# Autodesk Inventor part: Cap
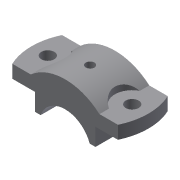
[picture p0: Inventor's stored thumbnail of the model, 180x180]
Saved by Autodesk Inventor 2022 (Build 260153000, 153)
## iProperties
Created: 2009-04
Part Number: Cap
Document SubType Name: Modeling
Designer: Sham
Density: 1 g/cm^3
Material: Generic
Appearance: Default
Author: Sham
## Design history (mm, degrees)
sketch "Sketch1"
  geometry: L1 (-48.857, 23)-(48.857, 23); L2 (48.857, -23)-(-48.857, -23); A1 r 54 centre (0, 0) between (-48.857, 23) and (-48.857, -23); A2 r 54 centre (0, 0) between (48.857, -23) and (48.857, 23); 1 further point
  constraints: 4 end point, 4 point on circle, 2 centre point, 2 coincident, 1 horizontal, 1 parallel, 1 other
  dimensions: "d3" = 54 radius of A1; "d4" = 54 radius of A2; "d5" = 46 distance between parallel lines of L2 L1; "d6" = 23 distance from line of point (0, 0) L1
extrude "Extrusion1" new body sketch "Sketch1" distance "d7" = 12; taper "d8" = 0 deg
sketch "Sketch3"
  geometry: L1 (20.906, 0)-(20.906, -16); L2 (76.906, -0.137)-(76.906, -16.137); L3 (20.906, -16)-(26.23, -16); L4 (71.532, -16.137)-(76.906, -16.137); L5 (76.906, -0.137)-(76.857, 12); L6 (97.714, 0)-(0, 0) reference; L7 (76.857, 12)-(80.606, 12); L8 (17.108, 12)-(20.906, 12); L9 (20.906, 12)-(20.906, 0); L10 (0, 12)-(97.714, 12) reference; A1 r 24 centre (48.857, -24) between (71.532, -16.137) and (26.23, -16); A2 r 48 centre (48.857, -24) between (80.606, 12) and (17.108, 12); 3 further points
  constraints: 16 end point, 4 point on circle, 3 parallel, 3 perpendicular, 2 centre point, 2 coincident, 2 vertical alignment, 1 collinear, 1 midpoint, 1 vertical, 2 other
  dimensions: "d17" = 48 diameter of A1; "d18" = 16 distance of L1.start L1.end; "d19" = 56 distance between parallel lines of L2 L1; "d21" = 8 vertical distance of A1.centre L1.end; "d22" = 48 radius of A2; "d23" = 0 distance from line of L6 L1.start; "d38" = 31.74902 distance of L7.end point (48.857, 12); "d39" = 28 distance from line of point (48.857, 12) L5
extrude "Extrusion2" join sketch "Sketch3" stored distance "d24" = 12; taper "d25" = 0 deg
sketch "Sketch4"
  geometry: 2 further points
  dimensions: "d26" = 78 distance of point (39, 0) point (-39, 0)
hole "Hole1" sketch "Sketch4" at (-39, 0), (39, 0) diameter "d28" = 12; stored, may be unused: countersink angle "d32" = 90 deg, drill point angle "d34" = 118 deg; dims "d29" = 6, "d30" = 4, "d31" = 2, "d33" = 8
sketch "Sketch5"
  geometry: L1 (-31.749, -23)-(-31.749, 23) reference; L2 (-31.749, 14.263)-(-31.749, -14.263); C1 r 6 at (-39, 0) reference; A1 r 16 centre (-39, 0) between (-31.749, -14.263) and (-31.749, 14.263)
  constraints: 2 end point, 2 point on circle, 1 centre point, 1 coincident, 1 collinear, 1 point on line
  dimensions: "d35" = 16 radius of A1
extrude "Extrusion3" cut sketch "Sketch5" distance "d36" = 12; taper "d37" = 0 deg
mirror "Mirror2"
workplane "Work Plane4"
sketch "Sketch6"
  geometry: L1 (-31.749, 0)-(31.749, 0) reference; 1 further point
  dimensions: "d40" = 23 distance from line of L1 point (0, 23)
hole "Hole2" sketch "Sketch6" at (0, 23) diameter "d41" = 6; stored, may be unused: countersink angle "d45" = 90 deg, drill point angle "d47" = 118 deg; dims "d42" = 6, "d43" = 8, "d44" = 16, "d46" = 8
body "Solid1"
